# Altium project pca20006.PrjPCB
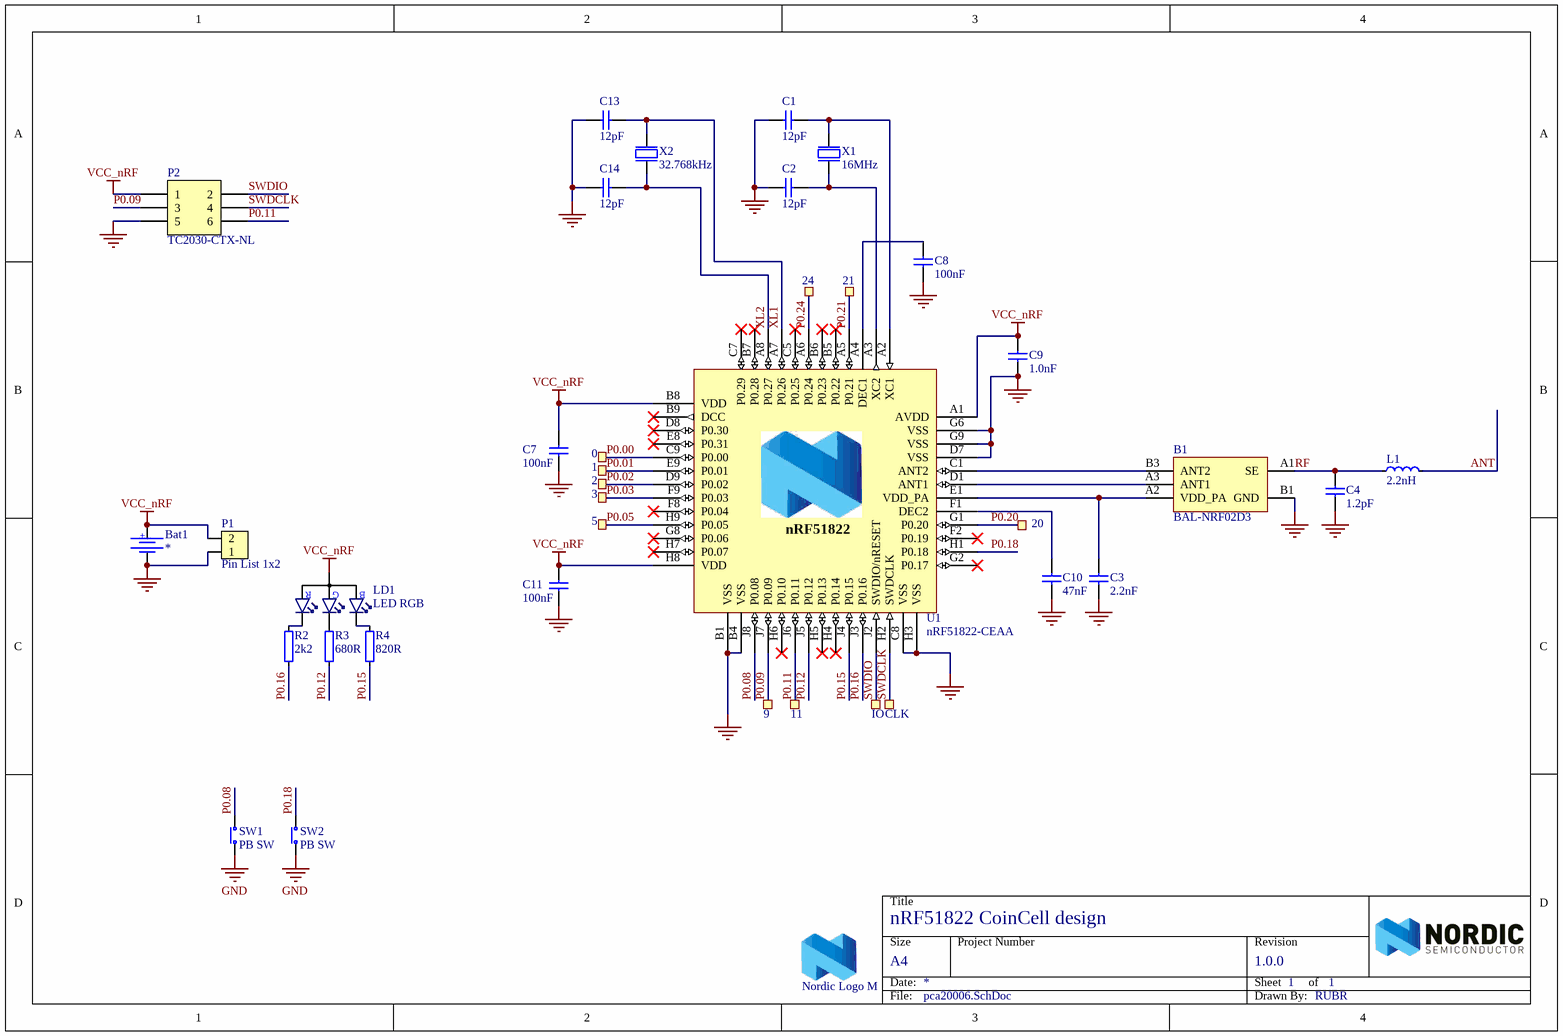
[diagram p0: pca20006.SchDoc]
1 sheet, 38 parts. Net scope: global (net labels, ports and power ports of the same name join across sheets).
Board file: 400059.PcbDoc

## Sheet pca20006.SchDoc: nRF51822 CoinCell design
size A4; Revision: 1.0.0; SheetNumber: 1; SheetTotal: 1; DrawnBy: RUBR; DocumentSize: A4; PCBRevision: 0138RUBR; PCAName: PCA20006; PCBNumber: 400059

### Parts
0  Ø1.0mm,SMD  [TP_SMD_Ø1.0mm]  (value not drawn)  (no BOM)
1  Ø1.0mm,SMD  [TP_SMD_Ø1.0mm]  (value not drawn)  (no BOM)
2  Ø1.0mm,SMD  [TP_SMD_Ø1.0mm]  (value not drawn)  (no BOM)
3  Ø1.0mm,SMD  [TP_SMD_Ø1.0mm]  (value not drawn)  (no BOM)
5  Ø1.0mm,SMD  [TP_SMD_Ø1.0mm]  (value not drawn)  (no BOM)
9  Ø1.0mm,SMD  [TP_SMD_Ø1.0mm]  (value not drawn)  (no BOM)
11  Ø1.0mm,SMD  [TP_SMD_Ø1.0mm]  (value not drawn)  (no BOM)
20  Ø1.0mm,SMD  [TP_SMD_Ø1.0mm]  (value not drawn)  (no BOM)
21  Ø1.0mm,SMD  [TP_SMD_Ø1.0mm]  (value not drawn)  (no BOM)
24  Ø1.0mm,SMD  [TP_SMD_Ø1.0mm]  (value not drawn)  (no BOM)
B1  BAL-NRF02D3  [BAL-ST-WLCSP]
Bat1  *  [CR1632_HOLDER_SMD]
C1  12pF  [CAPC1005X04L]
C2  12pF  [CAPC1005X04L]
C3  2.2nF  [CAPC1005X04L]
C4  1.2pF  [CAPC1005X04L]
C7  100nF  [CAPC1005X04L]
C8  100nF  [CAPC1005X04L]
C9  1.0nF  [CAPC1005X04L]
C10  47nF  [CAPC1005X04L]
C11  100nF  [CAPC1005X04L]
C13  12pF  [CAPC1005X04L]
C14  12pF  [CAPC1005X04L]
CLK  Ø1.0mm,SMD  [TP_SMD_Ø1.0mm]  (value not drawn)  (no BOM)
IO  Ø1.0mm,SMD  [TP_SMD_Ø1.0mm]  (value not drawn)  (no BOM)
L1  2.2nH  [INDC1005X04L]
LD1  LED RGB  [SML-LX0404SIUPGUSB]
LOGO1  Nordic Logo M  [NORDIC_LOGO_M]  (no BOM)
P1  Pin List 1x2  [LIST_1x2]
P2  TC2030-CTX-NL  [TC2030-IDC-NLFP]  (no BOM)
R2  2k2  [RESC1005X04L]
R3  680R  [RESC1005X04L]
R4  820R  [RESC1005X04L]
SW1  PB SW  [SW_TACTILE_2.6x3.0MM_4-LEAD]
SW2  PB SW  [SW_TACTILE_2.6x3.0MM_4-LEAD]
U1  nRF51822-CEAA  [BGA62C40P9X9_383X350X55]
X1  16MHz  [BT-XTAL_2520]
X2  32.768kHz  [FC-135]

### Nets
GND: B1.B1(GND) Bat1.2 C1.1 C2.1 C3.1 C4.1 C7.1 C8.2 C9.1 C10.1 C11.1 C13.1 C14.1 P1.1 P2.5 SW1.2(COM) SW2.2(COM) U1.B1(VSS) U1.B4(VSS) U1.C8(VSS) U1.D7(VSS) U1.G3(N.C.) U1.G4(N.C.) U1.G6(VSS) U1.G9(VSS) U1.H3(VSS) X1.2(GND) X1.4(GND)
VCC_nRF: Bat1.1 C7.2 C9.2 C11.2 LD1.4(A) P1.2 P2.1 U1.A1(AVDD) U1.B8(VDD) U1.H8(VDD)
ANT: L1.2
P0.00: 0.1 U1.C9(P0.00)
P0.01: 1.1 U1.E9(P0.01)
P0.02: 2.1 U1.D9(P0.02)
P0.03: 3.1 U1.F9(P0.03)
P0.05: 5.1 U1.H9(P0.05)
P0.08: SW1.1(N.O) U1.J8(P0.08)
P0.09: 9.1 P2.3 U1.J7(P0.09)
P0.11: 11.1 P2.6 U1.J6(P0.11)
P0.12: R3.1 U1.J5(P0.12)
P0.15: R4.1 U1.J4(P0.15)
P0.16: R2.1 U1.J3(P0.16)
P0.18: SW2.1(N.O) U1.H1(P0.18)
P0.20: 20.1 U1.G1(P0.20)
P0.21: 21.1 U1.A5(P0.21)
P0.24: 24.1 U1.A6(P0.24)
RF: B1.A1(SE) C4.2 L1.1
SWDCLK: CLK.1 P2.4 U1.H2(SWDCLK)
SWDIO: IO.1 P2.2 U1.J2(SWDIO/nRESET)
XL1: C13.2 U1.A7(P0.26) X2.1(inp)
XL2: C14.2 U1.A8(P0.27) X2.2(out)
NetB1_A2: B1.A2(VDD_PA) C3.2 U1.E1(VDD_PA)
NetB1_A3: B1.A3(ANT1) U1.D1(ANT1)
NetB1_B3: B1.B3(ANT2) U1.C1(ANT2)
NetC1_2: C1.2 U1.A2(XC1) X1.1(inp)
NetC2_2: C2.2 U1.A3(XC2) X1.3(out)
NetC8_1: C8.1 U1.A4(DEC1)
NetC10_2: C10.2 U1.F1(DEC2)
NetLD1_1: LD1.1(C_RED) R2.2
NetLD1_2: LD1.2(C_GREEN) R3.2
NetLD1_3: LD1.3(C_BLUE) R4.2

Not connected (* = marked no-connect by the designer): U1 B5(P0.22)* B6(P0.23)* B7(P0.28)* B9(DCC)* C5(P0.25)* C7(P0.29)* D8(P0.30)* E8(P0.31)* F2(P0.19)* F8(P0.04)* G2(P0.17)* G8(P0.06)* H4(P0.14)* H5(P0.13)* H6(P0.10)* H7(P0.07)*

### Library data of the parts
0-3 5 9 11 20 21 24 CLK IO = TP_SMD_Ø1.0MM: 1.0mm circular SMD testpad; Manufacturer: Nordic Semiconductor; Artikkelnr Noca: N.A.
B1 = BAL-NRF02D3: 50 ohm balun transformer for 2.45GHz ISM; Manufacturer: STMicroelectronics; Artikkelnr Noca: N.A.
Bat1 = Bat Holder CR1632 SMD: Manufacturer: Keystone; Manufacturer Part Number: 3012; 2nd source part number: 165-0697; Artikkelnr Noca: N.A.
C1 C2 C13 C14 = C0402-12p: Capacitor, NP0, ±2%; Note: 50V; Artikkelnr Noca: 20029159
C3 = C0402-2n2: Capacitor, X7R, ±10%; Note: 50V; Artikkelnr Noca: 20039221
C4 = C0402-1.2p: Capacitor, NP0, ±0.1pF; Note: 50V; Artikkelnr Noca: 20029157
C7 C8 C11 = C0402-100n: Capacitor, X7R, ±10%; Note: 16V; Artikkelnr Noca: 20039200
C9 = C0402-1n0: Capacitor, X7R, ±10%; Note: 50V; Artikkelnr Noca: 20039223
C10 = C0402-47n: Capacitor, X7R, ±10%; Note: Chip Cap 10%; Artikkelnr Noca: 20039389
L1 = L0402-2n2: Inductor, 220mA, ±0.1nH; Manufacturer: Murata; Manufacturer Part Number: LQP15MN2N2B02D; Note: High frequency chip inductor ±5%; Artikkelnr Noca: 33029257
LD1 = SML-LX0404SIUPGUSB: RGB LED 1.00 mm x 1.00 mm SMD; Manufacturer: Lumex; 2nd source part number: 211-8843; Artikkelnr Noca: 13019150
LOGO1 = Nordic Logo M: Nordic Logo, medium size; Artikkelnr Noca: N.A.
P1 = Pin List 1x2: Pin List 1x2, 2.54mm (100mil); Artikkelnr Noca: 56019040
P2 = TC2030-CTX-NL: CBL PLUG-OF-NAILS 6-PIN; Manufacturer: Tag-Connect LLC; Artikkelnr Noca: N.A.
R2 = R0402-2k2: Resistor, ±1%, 0.063W; Note: Chip Res 1%; Artikkelnr Noca: 27049081
R3 = R0402-680: Resistor, ±1%, 0.063W; Note: Chip Res 1%; Artikkelnr Noca: 27049069
R4 = R0402-820: Resistor, ±1%, 0.063W; Note: Chip Res 1%; Artikkelnr Noca: 27049071
SW1 SW2 = KMT021 NGJ LHS: Nano-Miniature Top Actuated Tact Switch with extended life 3.0x2.6mm; Manufacturer: C & K; 2nd source part number: 190-8260; Artikkelnr Noca: N.A.
U1 = nRF51822-CEAAD0: Multi-protocol Bluetooth Low Energy and 2.4GHz proprietary system-on-chip; Manufacturer: Nordic Semiconductor; Note: nRF51822 XLR2.4 - WLCSP62 3.8x3.5 0.4mm pitch; Artikkelnr Noca: N.A.
X1 = NX2520SA-16MHZ-STD-CSW-5: XTAL SMD 2520, 16MHz, 8pF, ±15ppm; Manufacturer: NDK; Note: XTAL SMD 16.000MHz; Artikkelnr Noca: 22019192
X2 = XTAL_FC-135 32.768k: EPSON TOYOCOM - FC-135 32.768KHZ ±20PPM,9.0PF - CRYSTAL, SM, WATCH; 2nd source part number: 127-8037; Note: XTAL SMD 32.768kHz, 3215; Artikkelnr Noca: 22019091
